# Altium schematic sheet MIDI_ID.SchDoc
size A4
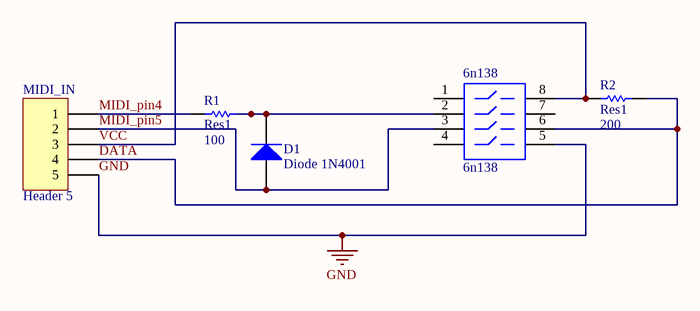
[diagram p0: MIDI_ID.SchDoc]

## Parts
6n138  6n138  [DIP-8]
D1  Diode 1N4001  [DO-41]
MIDI_IN  Header 5  [HDR1X5]
R1  Res1  value 100  [AXIAL-0.3]
R2  Res1  value 200  [AXIAL-0.3]

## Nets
GND: 6n138.5 MIDI_IN.5
DATA: 6n138.6 MIDI_IN.4 R2.2
MIDI_pin4: MIDI_IN.1 R1.1
MIDI_pin5: 6n138.3 D1.1(A) MIDI_IN.2
VCC: 6n138.8 MIDI_IN.3 R2.1
Net6n138_2: 6n138.2 D1.2(K) R1.2

Not connected (* = marked no-connect by the designer): 6n138 1 4 7

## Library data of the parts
6n138 = SW-DIP4
D1 = Diode 1N4001: 1 Amp General Purpose Rectifier
MIDI_IN = Header 5: Header, 5-Pin
R1 R2 = Res1: Resistor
